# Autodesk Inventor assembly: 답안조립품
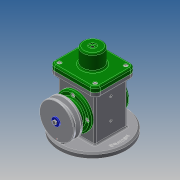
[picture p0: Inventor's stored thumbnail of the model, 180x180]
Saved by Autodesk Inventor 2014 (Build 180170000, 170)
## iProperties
Created: 2019-08
Part Number: 답안조립품
Document SubType Name: Assembly
Designer: kb542-16
Author: kb542-16
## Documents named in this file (18)
- C:\Users\kb542-16\Desktop\490804V1042\답안조립품.iam
- C:\Users\kb542-16\Desktop\490804V1042\본체.ipt
- C:\Users\kb542-16\Desktop\490804V1042\E-링.ipt
- C:\Users\kb542-16\Desktop\490804V1042\V-벨트풀리.ipt
- C:\Users\kb542-16\Desktop\490804V1042\덮개.ipt
- C:\Users\kb542-16\Desktop\490804V1042\뒤커버.ipt
- C:\Users\kb542-16\Desktop\490804V1042\링크.ipt
- C:\Users\kb542-16\Desktop\490804V1042\베어링 17 x 40 x 12.ipt
- C:\Users\kb542-16\Desktop\490804V1042\볼트 M4 x 8.ipt
- C:\Users\kb542-16\Desktop\490804V1042\볼트 M4 x 10.ipt
- C:\Users\kb542-16\Desktop\490804V1042\슬라이더.ipt
- C:\Users\kb542-16\Desktop\490804V1042\앞커버.ipt
- C:\Users\kb542-16\Desktop\490804V1042\오일 실 17 30 8.ipt
- C:\Users\kb542-16\Desktop\490804V1042\와셔 4x16.ipt
- C:\Users\kb542-16\Desktop\490804V1042\클레비스 핀 6 x 22.ipt
- 클레비스 핀 6 x 22.ipt
- C:\Users\kb542-16\Desktop\490804V1042\키 4 x 4 x 12.ipt
- C:\Users\kb542-16\Desktop\490804V1042\편심축.ipt
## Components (2 placed, 2 different names)
1. E-링:1
2. V-벨트풀리:1
